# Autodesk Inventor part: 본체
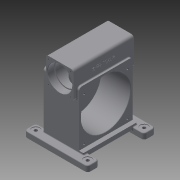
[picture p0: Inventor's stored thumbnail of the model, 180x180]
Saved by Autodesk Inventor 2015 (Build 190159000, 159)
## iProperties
Created: 2025-06
Part Number: 본체
Material: 일반
Document SubType Name: Modeling
Designer: User
Density: 1 g/cm^3
Appearance: 기본값
Author: User
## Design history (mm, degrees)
sketch "스케치1"
  geometry: L1 (-93, -103)-(93, -103); L2 (93, -103)-(93, 103); L3 (93, 103)-(-93, 103); L4 (-93, 103)-(-93, -103); L5 (-93, -103)-(93, 103); L6 (93, -103)-(-93, 103); 1 further point
  constraints: 12 end point, 2 midpoint, 2 parallel, 1 horizontal, 1 perpendicular
  dimensions: "d0" = 186 distance of L3.end L2.end; "d1" = 206 distance of L2.end L1.end
extrude "돌출1" new body sketch "스케치1" distance "d2" = 125; taper "d3" = 0 deg
sketch "스케치2"
  geometry: L1 (103, -93)-(103, 93) reference; L2 (103, 93)-(-103, 93) reference; L3 (103, -93)-(86, -93); L4 (86, -93)-(86, 93); L5 (86, 93)-(103, 93); L6 (103, 93)-(103, -93); 1 further point
  constraints: 8 end point, 2 parallel, 1 horizontal, 1 perpendicular, 1 point on line
  dimensions: "d4" = 17 distance between parallel lines of L1 L4
extrude "돌출2" join sketch "스케치2" distance "d5" = 15; taper "d6" = 0 deg
node "작업 평면1"
sketch "스케치3"
  geometry: L1 (-22, 158)-(-118, 158); L2 (-118, 158)-(-118, 62); L3 (-118, 62)-(-22, 62); L4 (-22, 62)-(-22, 158); L5 (-22, 158)-(-118, 62); L6 (-118, 158)-(-22, 62); L7 (0, -103)-(0, 103) reference; L8 (0, -103)-(-140, -103) reference; 2 further points
  constraints: 12 end point, 2 midpoint, 2 parallel, 1 horizontal, 1 perpendicular
  dimensions: "d8" = 96 distance of L3.end L2.end; "d9" = 96 distance of L2.end L1.end; "d10" = 70 distance from line of L7 point (-70, 110); "d11" = 261 distance between parallel lines of L8 L1
extrude "돌출3" join sketch "스케치3" stored distance "d12" = 210; taper "d13" = 0 deg
fillet "모깎기1" dims "d14" = 10
sketch "스케치4"
  geometry: A1 r 10 centre (108, -72) between (118, -72) and (108, -62) reference; A2 r 10 centre (32, -72) between (32, -62) and (22, -72) reference; A3 r 10 centre (32, -148) between (22, -148) and (32, -158) reference; A4 r 10 centre (108, -148) between (108, -158) and (118, -148) reference; 1 further point
hole "구멍1" sketch "스케치4" at (108, -148), (32, -148), (108, -72), (32, -72) diameter "d15" = 4.917; stored, may be unused: countersink angle "d19" = 90 deg, drill point angle "d21" = 118 deg; dims "d16" = 12, "d17" = 4, "d18" = 2, "d20" = 14
sketch "스케치5"
  geometry: L1 (32, -158)-(108, -158) reference; L2 (118, -148)-(118, -72) reference; 2 further points
  dimensions: "d22" = 48 distance from line of L2 point (70, -110); "d23" = 48 distance from line of L1 point (70, -110)
hole "구멍2" sketch "스케치5" at (70, -110) diameter "d24" = 77; stored, may be unused: countersink angle "d28" = 90 deg, drill point angle "d30" = 118 deg; dims "d25" = 16, "d26" = 85, "d27" = 23, "d29" = 18
sketch "스케치6"
  geometry: L1 (103, -93)-(103, 93) reference; C1 r 86 at (-10, 0); 1 further point
  constraints: 1 centre point, 1 horizontal alignment
  dimensions: "d31" = 172 diameter of C1; "d32" = 113 distance from line of L1 C1.centre
extrude "돌출4" cut sketch "스케치6" distance "d33" = 102; taper "d34" = 0 deg
sketch "스케치7"
  geometry: C1 r 86 at (0, 0) reference; 1 further point
hole "구멍3" sketch "스케치7" at (0, 0) diameter "d35" = 54; stored, may be unused: countersink angle "d39" = 90 deg, drill point angle "d41" = 0 deg; dims "d36" = 16, "d37" = 62, "d38" = 16, "d40" = 19
fillet "모깎기2" dims "d42" = 1
sketch "스케치8"
  geometry: L1 (0, 186)-(-140, 186) reference; L2 (-140, 0)-(-140, 186) reference; L3 (0, 0)-(-140, 0) reference; L4 (-170, -25)-(30, -25); L5 (40, -15)-(40, 5); L6 (30, 15)-(-170, 15); L7 (-180, 5)-(-180, -15); L8 (-70, 0)-(-70, 186); L9 (-140, 93)-(0, 93); L10 (-125, 7)-(-125, 179) reference; A1 r 10 centre (-170, -15) between (-180, -15) and (-170, -25); A2 r 10 centre (-170, 5) between (-170, 15) and (-180, 5); A3 r 10 centre (30, -15) between (30, -25) and (40, -15); A4 r 10 centre (30, 5) between (40, 5) and (30, 15)
  constraints: 12 end point, 8 point on circle, 8 tangent, 4 centre point, 3 equal radius, 3 midpoint, 2 parallel, 2 perpendicular, 1 horizontal
  dimensions: "d43" = 40 distance between parallel lines of L6 L4; "d44" = 10 radius of A1; "d45" = 220 distance between parallel lines of L5 L7; "d46" = 110 distance between parallel lines of L8 L7; "d47" = 118 distance from line of L4 L9.start
extrude "돌출5" join sketch "스케치8" stored distance "d48" = 20; taper "d49" = 0 deg
fillet "모깎기3" dims "d50" = 10
sketch "스케치9"
  geometry: 5 further points
  constraints: 2 horizontal alignment, 2 vertical alignment
  dimensions: "d51" = 75 horizontal distance of point (0, 0) point (-75, -75); "d52" = 75 horizontal distance of point (0, 0) point (-75, -75); "d53" = 150 distance of point (-75, 75) point (-75, -75); "d54" = 150 distance of point (75, -75) point (-75, -75)
hole "구멍4" sketch "스케치9" at (-75, -75), (-75, 75), (75, 75), (75, -75) diameter "d55" = 6.647; stored, may be unused: countersink angle "d59" = 90 deg, drill point angle "d61" = 118 deg; dims "d56" = 16, "d57" = 62, "d58" = 16, "d60" = 18
sketch "스케치10"
  geometry: L1 (0, 0)-(140, 0) reference; L2 (-30, -25)-(170, -25) reference; L3 (70, 0)-(70, -25); C1 r 14 at (-20, -5); C2 r 14 at (160, -5); 1 further point
  constraints: 2 centre point, 2 end point, 2 midpoint, 1 horizontal alignment
  dimensions: "d62" = 28 diameter of C1; "d63" = 28 diameter of C2; "d64" = 180 distance of C2.centre C1.centre; "d66" = 20 distance from line of L2 C1.centre; "d67" = 90 distance from line of L3 C1.centre
hole "구멍5" sketch "스케치10" at (-20, -5), (160, -5) diameter "d68" = 11; stored, may be unused: countersink angle "d72" = 90 deg, drill point angle "d74" = 0 deg; dims "d69" = 16, "d70" = 28, "d71" = 2, "d73" = 18
fillet "모깎기4" dims "d75" = 1.1
chamfer "모따기1" distance "d76" = 1; stored, may be unused: second distance "d77" = 2, angle "d78" = 45 deg
fillet "모깎기5" dims "d79" = 3
fillet "모깎기6" dims "d80" = 3
sketch "스케치11"
  geometry: L1 (-10, 210)-(-10, 0) reference; 2 further points
  constraints: 1 horizontal alignment, 1 other
  dimensions: "d81" = 30 distance from line of L1 point (20, 105)
feature "엠보싱1" sketch "스케치11" dims "d0" = 186, "d1" = 206, "d8" = 96, "d9" = 96, "d10" = 70, "d11" = 261, "d82" = 0.5, "d83" = 0
node "솔리드1"
mirror "대칭1"
mirror "대칭2"
mirror "대칭3"
mirror "대칭4"
other parameters: "d7" = 0
